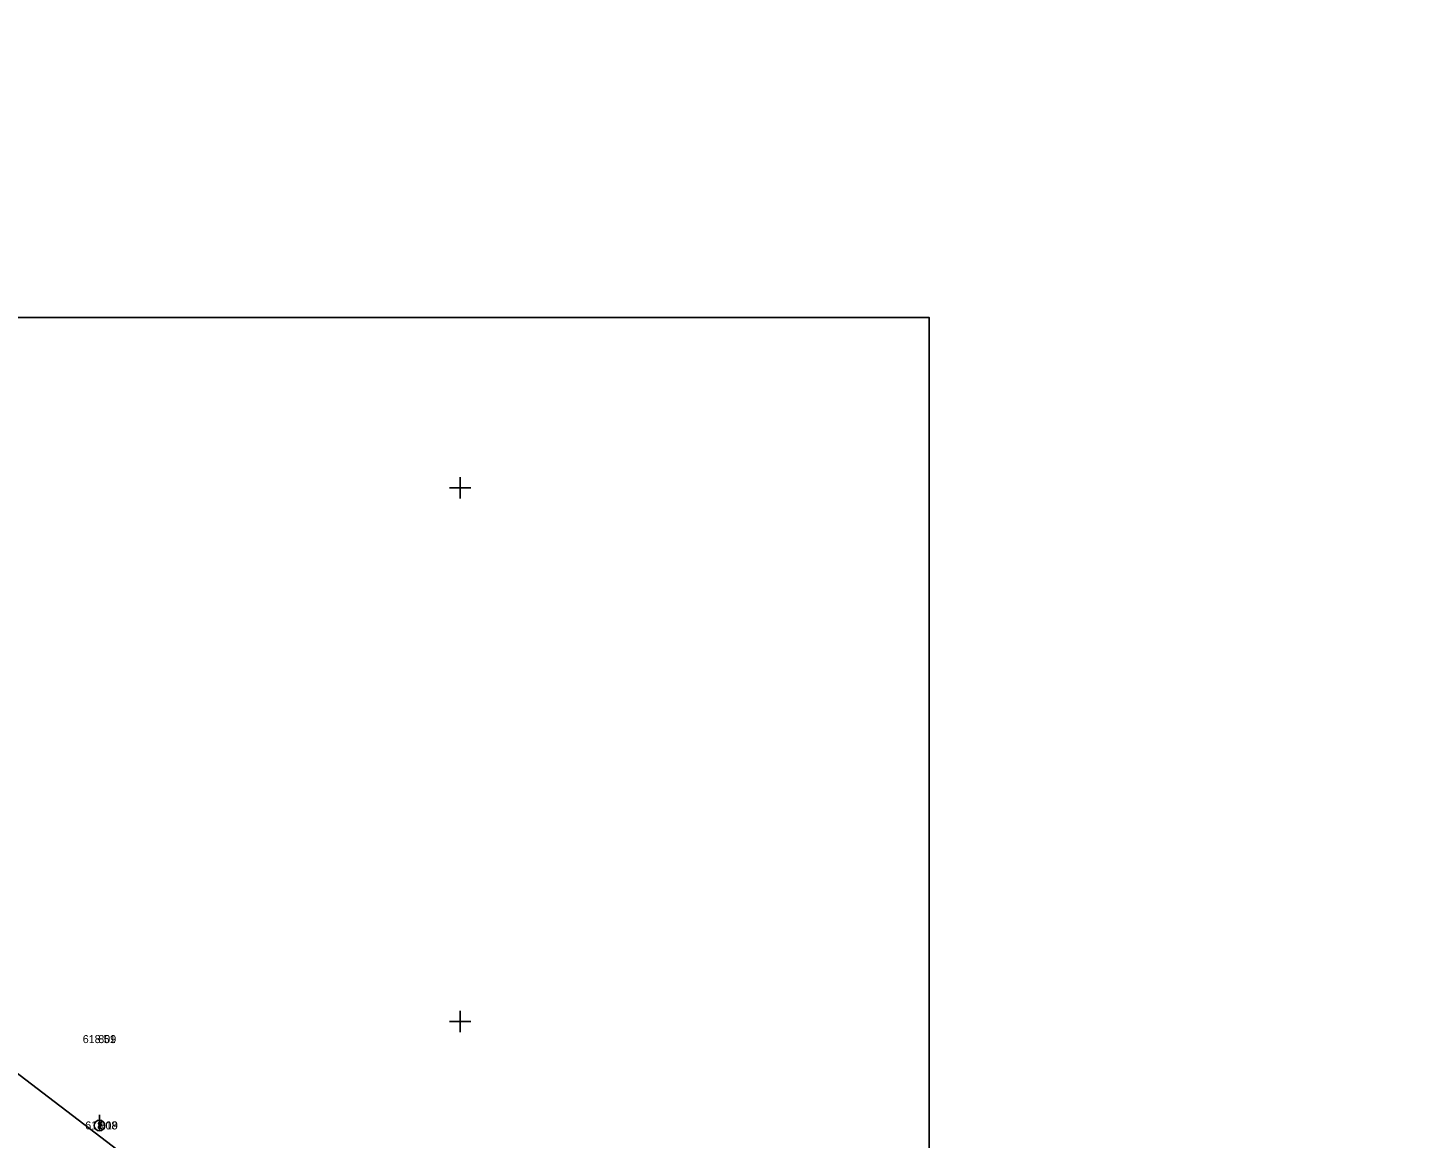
# Model space of a CAD drawing. Extents: x -844765 to -843273, y -997542 to -995529.
# Drawn here: x -843790.5 to -843660.1, y -997110.9 to -997006.9 of the extents above; entities that cross this region are included whole.
import ezdxf

# ---------------------------------------------------------------- set-up
doc = ezdxf.new("R2010")
doc.units = 0
for name, color, linetype in [('Doplněk polohopisu', 7, 'Continuous'), ('Osa', 7, 'Continuous'), ('Rámeček', 7, 'Continuous'), ('Sítě podzemní nerozlišené', 7, 'Continuous'), ('Vrstva 63', 7, 'Continuous'), ('Číslo bodu', 7, 'Continuous'), ('Řezy', 7, 'Continuous')]:
    doc.layers.add(name, color=color, linetype=linetype)

msp = doc.modelspace()

# ---------------------------------------------------------------- linework, layer by layer
at = {"layer": 'Doplněk polohopisu'}
msp.add_line((-843783.81, -997110.25), (-843783.81, -997108.75), dxfattribs=at)
msp.add_circle((-843783.81, -997109.75), 0.5, dxfattribs=at)
at = {"layer": 'Osa'}
msp.add_lwpolyline([(-843652.73, -997208.73), (-843685.02, -997184.17), (-843714.35, -997161.92), (-843737.99, -997144.05), (-843746.29, -997137.86), (-843747.28, -997137.77), (-843770.7, -997120.79), (-843797.77, -997100.1), (-843802.48, -997096.6), (-843818.53, -997084.86), (-843834.64, -997072.98), (-843843.67, -997065.86), (-843850.66, -997061.13), (-843858.57, -997054.8), (-843873.56, -997041.85), (-843881.27, -997036.04), (-843889.86, -997029.57), (-843897.98, -997023.38), (-843905.21, -997017.86), (-843921.14, -997005.98)], dxfattribs=at)
at = {"layer": 'Rámeček'}
for p, q in [((-843750, -997049), (-843750, -997051)), ((-843749, -997050), (-843751, -997050)), ((-843750, -997099), (-843750, -997101)), ((-843749, -997100), (-843751, -997100))]:
    msp.add_line(p, q, dxfattribs=at)
at = {"layer": 'Sítě podzemní nerozlišené'}
for p, q in [((-843783.92, -997101.65), (-843783.97, -997101.6)), ((-843783.92, -997101.65), (-843783.97, -997101.7)), ((-843783.92, -997101.65), (-843783.87, -997101.6)), ((-843783.92, -997101.65), (-843783.87, -997101.7)), ((-843783.81, -997109.75), (-843783.86, -997109.7)), ((-843783.81, -997109.75), (-843783.86, -997109.8)), ((-843783.81, -997109.75), (-843783.76, -997109.7)), ((-843783.81, -997109.75), (-843783.76, -997109.8))]:
    msp.add_line(p, q, dxfattribs=at)
at = {"layer": 'Vrstva 63'}
msp.add_lwpolyline([(-843896.06, -997176.53), (-843706.06, -997176.53), (-843706.06, -997034.03), (-843896.06, -997034.03)], close=True, dxfattribs=at)

# ---------------------------------------------------------------- texts
at = {"layer": 'Číslo bodu'}
for s, p in [('809', (-843783.92, -997102.03)), ('808', (-843783.81, -997110.12))]:
    msp.add_text(s, height=0.75, dxfattribs=at).set_placement(p)
at = {"layer": 'Řezy'}
for s, p in [('618.51', (-843785.38, -997102.03)), ('618.19', (-843785.15, -997110.12))]:
    msp.add_text(s, height=0.75, dxfattribs=at).set_placement(p)

doc.saveas('drawing.dxf')
